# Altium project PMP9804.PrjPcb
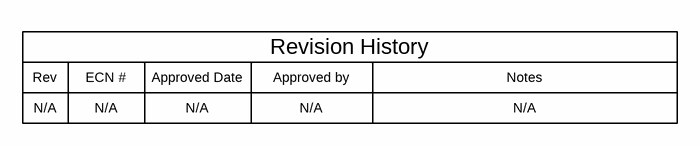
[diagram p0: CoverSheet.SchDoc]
CopyrightYear: 2016; EVM_Orderable: N/A; PCB_Layout: Who did the Layout?; PCB_Rev: E1; PRJ_Customer: Public Release; PRJ_Engineer: Enter name of project lead; PRJ_Number: TIDA-xxxxx; PRJ_Title: Change in menu Project|Project Options|Parameters; SCH_Rev: E1; TechSupport: http://www.ti.com/support; TID: ChangeMe!
3 sheets, 45 parts. Net scope: global (net labels, ports and power ports of the same name join across sheets).
Board file: TID.PcbDoc
Sheets:
  CoverSheet.SchDoc
  BlankSheet.SchDoc
  TID_Hardware.SchDoc

## Sheet CoverSheet.SchDoc
size 431 x 279 mm; Date: Not shown in title block; ApprovedBy: Not shown in title block; CheckedBy: Not shown in title block; Author: Not shown in title block; CompanyName: Not shown in title block; Engineer: Not shown in title block; Organization: Not shown in title block; Address1: Not shown in title block; Address2: Not shown in title block; Address3: Not shown in title block; Address4: Not shown in title block; DocumentNumber: 1; Revision: Use project parameter SCH_Rev; SheetNumber: 1; SheetTotal: 3; PageSetup: Record=PageOptions¦CenterHorizontal=True¦CenterVertical=True¦PrintScale=1.00¦XCorrection=1.00¦YCorrection=1.00¦PrintKind=0¦BorderSize=5000000¦LeftOffset=0¦BottomOffset=0¦Orientation=2¦PaperLength=1000¦PaperWidth=1000¦Scale=100¦PaperSource=15¦PrintQuality=600¦MediaType=1¦DitherType=10¦PaperKind=Letter¦PrintScaleMode=1

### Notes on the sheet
- Rev
- N/A
- ECN #
- Approved Date
- Approved by
- Revision History
- Notes

## Sheet BlankSheet.SchDoc
size 431 x 279 mm; Date: Not shown in title block; ApprovedBy: Not shown in title block; CheckedBy: Not shown in title block; Author: Not shown in title block; CompanyName: Not shown in title block; Engineer: Not shown in title block; Organization: Not shown in title block; Address1: Not shown in title block; Address2: Not shown in title block; Address3: Not shown in title block; Address4: Not shown in title block; DocumentNumber: 1; Revision: Use project parameter SCH_Rev; SheetNumber: 2; SheetTotal: 3; PageSetup: Record=PageOptions¦CenterHorizontal=True¦CenterVertical=True¦PrintScale=0.64¦XCorrection=1.00¦YCorrection=1.00¦PrintKind=0¦BorderSize=5000000¦LeftOffset=0¦BottomOffset=0¦Orientation=2¦PaperLength=1000¦PaperWidth=1000¦Scale=100¦PaperSource=15¦PrintQuality=600¦MediaType=1¦DitherType=10¦PrintScaleMode=1¦PaperKind=Letter
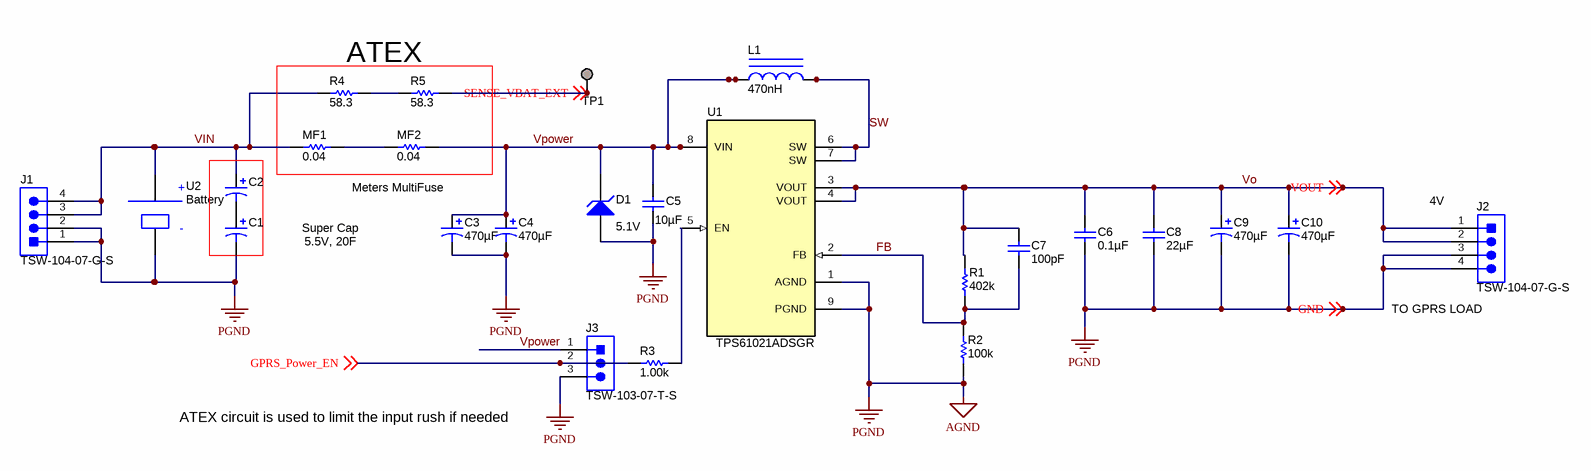
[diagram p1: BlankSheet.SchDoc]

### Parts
C1  EEU-FC1H222  [FC_1800x3550]  (value not drawn)
C2  EEU-FC1H222  [FC_1800x3550]  (value not drawn)
C3  ValueDisplayed: 470µF  [SEPC_C9]  (hidden comment: 6SEPC470MW)
C4  ValueDisplayed: 470µF  [SEPC_C9]  (hidden comment: 6SEPC470MW)
C5  ValueDisplayed: 10µF  [0603]  (hidden comment: GRM188R60J106ME84)
C6  ValueDisplayed: 0.1µF  [0603]  (hidden comment: GRM188R71C104KA01D)
C7  ValueDisplayed: 100pF  [0201_033]  (hidden comment: C0603C0G1E101J030BA)
C8  ValueDisplayed: 22µF  [0603]  (hidden comment: C1608X5R0J226M080AC)
C9  ValueDisplayed: 470µF  [SEPC_C9]  (hidden comment: 6SEPC470MW)
C10  ValueDisplayed: 470µF  [SEPC_C9]  (hidden comment: 6SEPC470MW)
D1  value 5.1V  [SMB]  (hidden comment: 1SMB5918BT3G)
J1  TSW-104-07-G-S  [TSW-104-07-G-S]
J2  TSW-104-07-G-S  [TSW-104-07-G-S]
J3  TSW-103-07-T-S  [Samtec_TSW-103-07-T-S]
L1  ValueDisplayed: 470nH  [XFL4015]  (hidden comment: XFL4015-471MEC)
MF1  ValueDisplayed: 0.04  [2010]  (hidden comment: CSRN2010FK40L0)
MF2  ValueDisplayed: 0.04  [2010]  (hidden comment: CSRN2010FK40L0)
R1  ValueDisplayed: 402k  [0603]  (hidden comment: RC0603FR-07402KL)
R2  ValueDisplayed: 100k  [0603]  (hidden comment: CPF0603B100KE)
R3  ValueDisplayed: 1.00k  [0603]  (hidden comment: CRCW06031K00FKEA)
R4  ValueDisplayed: 58.3  [0603]  (hidden comment: RT0603BRD0758R3L)
R5  ValueDisplayed: 58.3  [0603]  (hidden comment: RT0603BRD0758R3L)
TP1  Suggest using a net name here  [Keystone1502-2]  (value not drawn)
U1  TPS61021ADSGR  [DSG0008A]
U2  Battery

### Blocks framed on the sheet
ATEX: MF1 MF2 R4 R5

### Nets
AGND: C1.2(-) C3.2(-) C4.2(-) C5.2 C6.2 C8.2 C9.2(-) C10.2(-) D1.2(A) J1.1 J1.2 J2.3 J2.4 J3.3 R2.1 U1.1(AGND) U1.9(PGND) U2.2 ; off-sheet GND  [also labelled GND, PGND]
FB: C7.2 R1.1 R2.2 U1.2(FB)
GPRS_Power_EN: J3.2 R3.1 ; off-sheet GPRS_Power_EN
SENSE_VBAT_EXT: R5.2 TP1.1 ; off-sheet SENSE_VBAT_EXT
SW: L1.2 U1.6(SW) U1.7(SW)
VIN: C2.1(+) J1.3 J1.4 MF1.1 R4.1 U2.1
Vo: C6.1 C7.1 C8.1 C9.1(+) C10.1(+) J2.1 J2.2 R1.2 U1.3(VOUT) U1.4(VOUT) ; off-sheet VOUT  [also labelled VOUT]
Vpower: C3.1(+) C4.1(+) C5.1 D1.1(K) J3.1 L1.1 MF2.2 U1.8(VIN)
NetC1_1: C1.1(+) C2.2(-)
NetMF1_2: MF1.2 MF2.1
NetR3_2: R3.2 U1.5(EN)
NetR4_2: R4.2 R5.1

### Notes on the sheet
- Meters MultiFuse
- (near J2) 4V
- Super Cap
- 5.5V, 20F
- (near J2) TO GPRS LOAD
- ATEX circuit is used to limit the input rush if needed

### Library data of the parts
C1 = EEU-FC1H222: KAMAP, 2.7V, 40F; Manufacturer: Panasonic; Polarized: Y; CompType: Capacitor; Value: 2200uF; ValueDisplayed: 2200µF; U/M: EA; Cap_F: 0.0022; Tolerance_%: 20; Value1: 0.023 ohm; VDC_V: 50; Value2: 50V; ESR_ohm: 0.023; IRMS_A: 3.1; TaMin_C: -55; TaMax_C: 105; Cap_Case: 18x35.5mm; AEC Category: Q200; AEC Grade: 2
C2 = EEU-FC1H222: KAMAP 2.7V, 40F; Manufacturer: Panasonic; Polarized: Y; CompType: Capacitor; Value: 2200uF; ValueDisplayed: 2200µF; U/M: EA; Cap_F: 0.0022; Tolerance_%: 20; Value1: 0.023 ohm; VDC_V: 50; Value2: 50V; ESR_ohm: 0.023; IRMS_A: 3.1; TaMin_C: -55; TaMax_C: 105; Cap_Case: 18x35.5mm; AEC Category: Q200; AEC Grade: 2
C3 C4 C9 C10 = 6SEPC470MW: CAP, AL, 470 µF, 6.3 V, +/- 20%, 0.007 ohm, TH; Manufacturer: Panasonic; Polarized: Y; CompType: Capacitor; Value: 470uF; U/M: EA; Cap_F: 0.00047; Tolerance_%: 20; VDC_V: 6.3; Value2: 6.3V; ESR_ohm: 0.007; IRMS_A: 5.6; TaMin_C: -55; TaMax_C: 105; Cap_Case: 6.3x9; AEC Category: Q200
C5 = GRM188R60J106ME84: CAP, CERM, 10 µF, 6.3 V, +/- 20%, X5R, 0603; Manufacturer: MuRata; Polarized: N; CompType: Capacitor; Value: 10uF; U/M: EA; Cap_F: 0.00001; Tolerance_%: 20; Value1: Unknown; VDC_V: 6.3; Value2: 6.3V; TaMin_C: -55; TaMax_C: 85
C6 = GRM188R71C104KA01D: CAP, CERM, 0.1 µF, 16 V, +/- 10%, X7R, 0603; Manufacturer: MuRata; Polarized: N; CompType: Capacitor; Value: 0.1uF; U/M: EA; Cap_F: 0.0000001; Tolerance_%: 10; Value1: Unknown; VDC_V: 16; Value2: 16V; TaMin_C: -55; TaMax_C: 125
C7 = C0603C0G1E101J030BA: CAP, CERM, 100 pF, 25 V, +/- 5%, C0G/NP0, 0201; Manufacturer: TDK; Polarized: N; CompType: Capacitor; Value: 100pF; U/M: EA; Cap_F: 0.0000000001; Tolerance_%: 5; Value1: Unknown; VDC_V: 25; Value2: 25V; TaMin_C: -55; TaMax_C: 125; Cap_Case: 0201; AEC Category: Q200
C8 = C1608X5R0J226M080AC: CAP, CERM, 22 µF, 6.3 V, +/- 20%, X5R, 0603; Manufacturer: TDK; Polarized: N; CompType: Capacitor; Value: 22uF; U/M: EA; Cap_F: 0.000022; Tolerance_%: 20; Value1: Unknown; VDC_V: 6.3; Value2: 6.3V; TaMin_C: -55; TaMax_C: 85; AEC Category: Q200
D1 = 1SMB5918BT3G: Diode, Zener, 5.1 V, 550 mW, SMB; Manufacturer: ON Semiconductor; SymbolCreator: a0412235; U/M: EA; Power_W: 0.55; Vz_V: 5.1; Value1: 0.55W; RJA_CperW: 226; AEC Category: Q101
J1 J2 = TSW-104-07-G-S: Header, 100mil, 4x1, Gold, TH; Manufacturer: Samtec; SymbolCreator: a0412235; Pitch_mm: 2.54; Gender: Male; Shrouded: N; Row_Count: 1; Current_A: 6.3; Voltage_V: 550; Cert_CSA: Y
J3 = TSW-103-07-T-S: Header, 2.54 mm, 3x1, Tin, TH; Manufacturer: Samtec; SymbolCreator: a0799628; Pitch_mm: 2.54; Gender: Male; Shrouded: N; Row_Count: 1; Current_A: 6.3; Voltage_V: 550; Cert_CSA: Y
L1 = XFL4015-471MEC: Inductor, Shielded, Composite, 470 nH, 3.5 A, 0.0076 ohm, SMD; Manufacturer: Coilcraft; Value: 470nH; Ind_H: 470.0E-9; Imax_A: 3.5; Irms: 9.1A @ 20C rise; Isat: 3.5A @ 10% inductance drop; DCR_ohm: 0.0076; Value2: 3.5A; AEC Category: Q200
MF1 MF2 = CSRN2010FK40L0: RES, 0.04, 1%, 1 W, 2010; Manufacturer: Stackpole Electronics Inc; CompType: Resistor; Value: 0.04; Value_Code: R040; Tolerance_%: 1; Value2: 1W; TempCo: 250 ppm/C; U/M: EA; AEC Category: Q200
R1 = RC0603FR-07402KL: RES, 402 k, 1%, 0.1 W, 0603; Manufacturer: Yageo America; CompType: Resistor; Value: 402k; Res_ohm: 402000; Tolerance_%: 1; Power_W: 0.1; Value2: 0.1W; VDC_V: 150; TempCo: 200 ppm/C; EIA_Code: E96; U/M: EA; AEC Category: Q200
R2 = CPF0603B100KE: RES, 100 k, 0.1%, 0.063 W, 0603; Manufacturer: TE Connectivity; CompType: Resistor; Value: 100k; Res_ohm: 100000; Tolerance_%: 0.1; Power_W: 0.063; Value2: 0.063W; VDC_V: 50; TempCo: 25 ppm/C; EIA_Code: E192; U/M: EA
R3 = CRCW06031K00FKEA: RES, 1.00 k, 1%, 0.1 W, 0603; Manufacturer: Vishay-Dale; CompType: Resistor; Value: 1.00k; Res_ohm: 1000; Value_Code: 1k00; Tolerance_%: 1; Power_W: 0.1; Value2: 0.1W; VDC_V: 75; TempCo: 100 ppm/C; EIA_Code: E96; U/M: EA; AEC Category: Q200
R4 R5 = RT0603BRD0758R3L: RES, 58.3, 0.1%, 0.1 W, 0603; Manufacturer: Yageo America; CompType: Resistor; Value: 58.3; Value_Code: 58R3; Tolerance_%: 0.1; Value2: 0.1W; VDC_V: 75; TempCo: 25 ppm/C; EIA_Code: E192; U/M: EA; AEC Category: Q200
TP1 = 1502-2: Terminal, Turret, TH, Double; Manufacturer: Keystone; CompType: Turret Terminal
U1 = TPS61021DSGR: 3-A BOOST CONVERTER WITH 0.5V ULTRA-LOW INPUT VOLTAGE, DSG0008A; Alternate PartNumber: TPS61021DSGT; Manufacturer: Texas Instruments; SymbolCreator: Altium; CompType: IC; U/M: EA
U2 = Component_1: Manufacturer: Used in BOM report; SymbolVersion: use current date i.e. 2008-05-20; SymbolCreator: Use a-id; CompType: Used in some BOM reports.  Useful for finding later.; U/M: EA, IN, or GM

## Sheet TID_Hardware.SchDoc
size 431 x 279 mm; Date: Not shown in title block; ApprovedBy: Not shown in title block; CheckedBy: Not shown in title block; Author: Not shown in title block; CompanyName: Not shown in title block; Engineer: Not shown in title block; Organization: Not shown in title block; Address1: Not shown in title block; Address2: Not shown in title block; Address3: Not shown in title block; Address4: Not shown in title block; DocumentNumber: 1; Revision: Use project parameter SCH_Rev; SheetNumber: 3; SheetTotal: 3; PageSetup: Record=PageOptions¦CenterHorizontal=True¦CenterVertical=True¦PrintScale=1.00¦XCorrection=1.00¦YCorrection=1.00¦PrintKind=0¦BorderSize=5000000¦LeftOffset=0¦BottomOffset=0¦Orientation=2¦PaperLength=1000¦PaperWidth=1000¦Scale=100¦PaperSource=15¦PrintQuality=600¦MediaType=1¦DitherType=10¦PaperKind=Letter¦PrintScaleMode=1
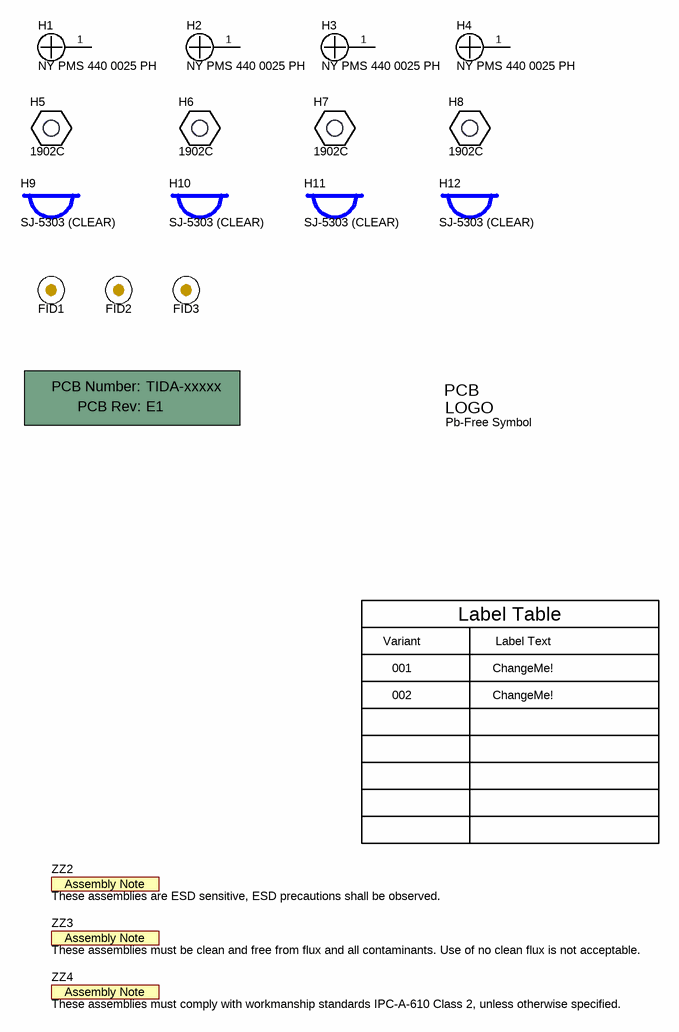
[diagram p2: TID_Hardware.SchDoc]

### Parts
!PCB  Printed Circuit Board  (value not drawn)  (mechanical)
FID1  Fiducial  [Fiducial10-20]  (value not drawn)
FID2  Fiducial  [Fiducial10-20]  (value not drawn)
FID3  Fiducial  [Fiducial10-20]  (value not drawn)
H1  NY PMS 440 0025 PH  [NY PMS 440 0025 PH]
H2  NY PMS 440 0025 PH  [NY PMS 440 0025 PH]
H3  NY PMS 440 0025 PH  [NY PMS 440 0025 PH]
H4  NY PMS 440 0025 PH  [NY PMS 440 0025 PH]
H5  1902C  [Keystone_1902C]
H6  1902C  [Keystone_1902C]
H7  1902C  [Keystone_1902C]
H8  1902C  [Keystone_1902C]
H9  SJ-5303 (CLEAR)  [Bumpon_SJ5003Transparent]
H10  SJ-5303 (CLEAR)  [Bumpon_SJ5003Transparent]
H11  SJ-5303 (CLEAR)  [Bumpon_SJ5003Transparent]
H12  SJ-5303 (CLEAR)  [Bumpon_SJ5003Transparent]
Logo2  Pb-Free Symbol  [Pb-Free_Overlay_Small]  (no BOM)
ZZ2  These assemblies are ESD sensitive, ESD precautions shall be observed.  [AssemblyNote]  (no BOM)
ZZ3  These assemblies must be clean and free from flux and all contaminants. Use of no clean flux is not acceptable.  [AssemblyNote]  (no BOM)
ZZ4  These assemblies must comply with workmanship standards IPC-A-610 Class 2, unless otherwise specified.  [AssemblyNote]  (no BOM)

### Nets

Not connected (* = marked no-connect by the designer): H1 1; H2 1; H3 1; H4 1

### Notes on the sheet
- Variant
- Label Table
- Label Text
- 001
- 002
- ChangeMe!

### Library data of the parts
!PCB = PCB: Manufacturer: Any; PartNumber: TIDA-xxxxx; SymbolCreator: a0412235
FID1-FID3 = Fiducial: Fiducial mark.  There is nothing to buy or mount.; SymbolCreator: codlsc
H1-H4 = NY PMS 440 0025 PH: Machine Screw, Round, #4-40 x 1/4, Nylon, Philips panhead; Manufacturer: B&F Fastener Supply; CompType: Hardware; SymbolCreator: codlsc; U/M: EA
H5-H8 = 1902C: Standoff, Hex, 0.5"L #4-40 Nylon; Manufacturer: Keystone; CompType: Hardware
H9-H12 = SJ-5303 (CLEAR): Bumpon, Hemisphere, 0.44 X 0.20, Clear; Manufacturer: 3M; SymbolCreator: a0412235
Logo2 = Pb-Free: SymbolCreator: a0412235
ZZ2-ZZ4 = AssemblyNote: SymbolCreator: codlsc

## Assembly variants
001: not fitted FID1 FID2 FID3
